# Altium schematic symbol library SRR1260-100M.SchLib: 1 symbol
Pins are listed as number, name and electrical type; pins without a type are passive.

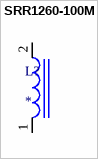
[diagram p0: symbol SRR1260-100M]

## SRR1260-100M
designator L?
Inductor Power Shielded Wirewound 33uH 20% 100KHz 27Q-Factor Ferrite 3A 60mOhm DCR T/R; MF: {'manufacturer': u'Bourns'}; MP: SRR1260-100M
footprint INDP125125X600N
pins: 1, 2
